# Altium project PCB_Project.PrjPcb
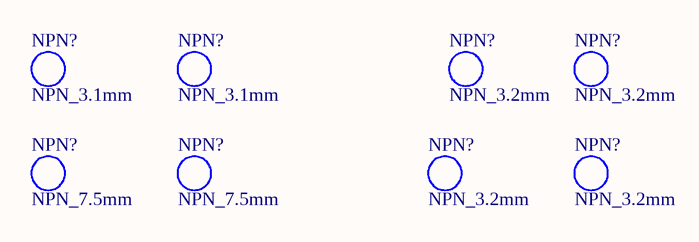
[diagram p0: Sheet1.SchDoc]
1 sheet, 8 parts. Net scope: global (net labels, ports and power ports of the same name join across sheets).
Board file: PCB2.PcbDoc

## Sheet Sheet1.SchDoc
size A4; SheetNumber: 1; SheetTotal: 1

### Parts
(Parts that share a designator on the sheet are numbered #1, #2 ... from top to bottom, then left to right.)
NPN?#1  NPN_3.1mm  [HOLE_NPH_3.1_LED_3mm]
NPN?#2  NPN_3.1mm  [HOLE_NPH_3.1_LED_3mm]
NPN?#3  NPN_3.2mm  [HOLE_NPH_3.2_M3]
NPN?#4  NPN_3.2mm  [HOLE_NPH_3.2_M3]
NPN?#5  NPN_7.5mm  [HOLE_NPH_7.5_F01]
NPN?#6  NPN_7.5mm  [HOLE_NPH_7.5_F01]
NPN?#7  NPN_3.2mm  [HOLE_NPH_3.2_M3]
NPN?#8  NPN_3.2mm  [HOLE_NPH_3.2_M3]

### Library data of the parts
NPN?#1 NPN?#2 = NPH_3.1mm_LED_3mm
NPN?#3 NPN?#4 NPN?#7 NPN?#8 = NPH_3.2mm_M3
NPN?#5 NPN?#6 = NPH_7.5mm_F01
